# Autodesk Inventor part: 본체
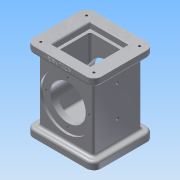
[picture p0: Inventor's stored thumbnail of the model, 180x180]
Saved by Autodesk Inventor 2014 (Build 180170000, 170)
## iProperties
Created: 2017-08
Part Number: 본체
Material: 알루미늄 6061
Document SubType Name: Modeling
Designer: 학생용
Density: 2.71 g/cm^3
Appearance: 알루미늄 - 평지
Mass: 872.328 g
Surface Area: 642.254 cm^2
Volume: 321.892 cm^3
Author: 학생용
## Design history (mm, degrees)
sketch "스케치1"
  geometry: L1 (46, -41)-(-46, -41); L2 (-46, -41)-(-46, 41); L3 (-46, 41)-(46, 41); L4 (46, 41)-(46, -41); L5 (46, -41)-(-46, 41); L6 (-46, -41)-(46, 41); 1 further point
  constraints: 12 end point, 2 midpoint, 2 parallel, 1 horizontal, 1 perpendicular
  dimensions: "d0" = 92 distance of L2.end L3.end; "d1" = 82 distance of L1.end L2.end
extrude "돌출1" new body sketch "스케치1" distance "d2" = 10; taper "d3" = 0 deg
sketch "스케치2"
  geometry: L1 (37, -33)-(-37, -33); L2 (-37, -33)-(-37, 33); L3 (-37, 33)-(37, 33); L4 (37, 33)-(37, -33); L5 (37, -33)-(-37, 33); L6 (-37, -33)-(37, 33); 1 further point
  constraints: 12 end point, 2 midpoint, 2 parallel, 1 horizontal, 1 perpendicular
  dimensions: "d4" = 74 distance of L2.end L3.end; "d5" = 66 distance of L1.end L2.end
extrude "돌출2" join sketch "스케치2" distance "d6" = 88; taper "d7" = 0 deg
sketch "스케치3"
  geometry: L1 (46, -41)-(-46, -41); L2 (-46, -41)-(-46, 41); L3 (-46, 41)-(46, 41); L4 (46, 41)-(46, -41); L5 (46, -41)-(-46, 41); L6 (-46, -41)-(46, 41); 1 further point
  constraints: 12 end point, 2 midpoint, 2 parallel, 1 horizontal, 1 perpendicular
  dimensions: "d8" = 92 distance of L2.end L3.end; "d9" = 82 distance of L1.end L2.end
extrude "돌출3" join sketch "스케치3" distance "d10" = 10; taper "d11" = 0 deg
sketch "스케치5"
  geometry: L1 (24, -24)-(-24, -24); L2 (-24, -24)-(-24, 24); L3 (-24, 24)-(24, 24); L4 (24, 24)-(24, -24); L5 (24, -24)-(-24, 24); L6 (-24, -24)-(24, 24); 1 further point
  constraints: 12 end point, 2 midpoint, 2 parallel, 1 horizontal, 1 perpendicular
  dimensions: "d12" = 48 distance of L2.end L3.end; "d13" = 48 distance of L1.end L2.end
extrude "돌출4" cut sketch "스케치5" distance "d14" = 16; taper "d15" = 0 deg
sketch "스케치6"
  geometry: L1 (26, -26)-(-26, -26); L2 (-26, -26)-(-26, 26); L3 (-26, 26)-(26, 26); L4 (26, 26)-(26, -26); L5 (26, -26)-(-26, 26); L6 (-26, -26)-(26, 26); 1 further point
  constraints: 12 end point, 2 midpoint, 2 parallel, 1 horizontal, 1 perpendicular
  dimensions: "d16" = 52 distance of L2.end L3.end; "d17" = 52 distance of L1.end L2.end
extrude "돌출5" cut sketch "스케치6" distance "d18" = 8; taper "d19" = 0 deg
fillet "모깎기1" dims "d20" = 10
chamfer "모따기1" distance "d21" = 1; stored, may be unused: second distance "d22" = 2, angle "d23" = 45 deg
sketch "스케치7"
  geometry: L1 (22, -22)-(-22, -22); L2 (-22, -22)-(-22, 22); L3 (-22, 22)-(22, 22); L4 (22, 22)-(22, -22); L5 (22, -22)-(-22, 22); L6 (-22, -22)-(22, 22); 1 further point
  constraints: 12 end point, 2 midpoint, 2 parallel, 1 horizontal, 1 perpendicular
  dimensions: "d24" = 44 distance of L2.end L3.end; "d25" = 44 distance of L1.end L2.end
extrude "돌출6" cut sketch "스케치7" distance "d26" = 74; taper "d27" = 0 deg
fillet "모깎기2" dims "d28" = 3
fillet "모깎기3" dims "d29" = 3
fillet "모깎기4" dims "d30" = 3
fillet "모깎기5" dims "d31" = 3
fillet "모깎기6" dims "d32" = 3
sketch "스케치8"
  geometry: A1 r 10 centre (-36, 31) between (-36, 41) and (-46, 31) reference; 2 further points
  constraints: 1 coincident
hole "구멍1" sketch "스케치8" at (-36, 31) diameter "d33" = 3.242; stored, may be unused: countersink angle "d37" = 90 deg, drill point angle "d39" = 118 deg; dims "d34" = 4, "d35" = 4, "d36" = 2, "d38" = 6
sketch "스케치9"
  geometry: A1 r 10 centre (-36, 31) between (-36, 41) and (-46, 31) reference; 2 further points
  constraints: 1 coincident
hole "구멍2" sketch "스케치9" at (-36, 31) diameter "d46" = 3.242; stored, may be unused: countersink angle "d50" = 90 deg, drill point angle "d52" = 118 deg; dims "d47" = 4, "d48" = 4, "d49" = 2, "d51" = 6
fillet "모깎기7" dims "d59" = 3
fillet "모깎기8" dims "d60" = 3
sketch "스케치10"
  geometry: L1 (70, -95)-(-2, -95) reference; C1 r 35 at (34, -41); 2 further points
  constraints: 1 centre point, 1 midpoint, 1 vertical alignment
  dimensions: "d61" = 70 diameter of C1; "d62" = 54 distance from line of L1 C1.centre
extrude "돌출7" cut sketch "스케치10" distance "d63" = 3; taper "d64" = 0 deg
node "작업 평면1"
sketch "스케치11"
  geometry: C1 r 35 at (0, 0) reference; C2 r 24 at (0, 0); 1 further point
  constraints: 1 centre point, 1 coincident
  dimensions: "d65" = 48 diameter of C2
extrude "돌출8" cut sketch "스케치11" stored distance "d66" = 3; taper "d67" = 0 deg
sketch "스케치12" dims "d68" = 58
  geometry: C1 r 35 at (0, 0) reference; 3 further points
  constraints: 2 horizontal alignment, 1 coincident, 2 other
hole "구멍3" sketch "스케치12" at (29, 0) diameter "d69" = 3.242; stored, may be unused: countersink angle "d73" = 90 deg, drill point angle "d75" = 118 deg; dims "d70" = 4, "d71" = 4, "d72" = 2, "d74" = 6
sketch "스케치13"
  geometry: L1 (0, 0)-(72, 0) reference; L2 (-10, 0)-(-10, -7) reference; 2 further points
  constraints: 1 other
  dimensions: "d79" = 46 distance from line of point (36, -4) L2; "d80" = 4 distance from line of L1 point (36, -4)
feature "엠보싱1" sketch "스케치13" dims "d8" = 92, "d9" = 82, "d81" = 0.5, "d82" = 0
sketch "스케치14"
  geometry: L1 (0, 0)-(0, 60) reference; L2 (95, 30)-(0, 30); L3 (-13, -1)-(-13, 61) reference; L4 (95, 61)-(95, -1) reference; 1 further point
  constraints: 2 end point, 1 midpoint, 1 point on line
  dimensions: "d83" = 38 distance from line of point (57, 30) L4
hole "구멍4" sketch "스케치14" at (57, 30) diameter "d84" = 4.134; stored, may be unused: countersink angle "d88" = 90 deg, drill point angle "d90" = 118 deg; dims "d85" = 4, "d86" = 4, "d87" = 2, "d89" = 6
sketch "스케치15"
  geometry: L1 (0, 0)-(0, 60) reference; L2 (95, 30)-(0, 30); C1 r 2.067 at (57, 30) reference; 1 further point
  constraints: 2 end point, 1 midpoint, 1 point on line
  dimensions: "d91" = 42 distance of point (15, 30) C1.centre
hole "구멍5" sketch "스케치15" at (15, 30) diameter "d92" = 4.134; stored, may be unused: countersink angle "d96" = 90 deg, drill point angle "d98" = 118 deg; dims "d93" = 4, "d94" = 4, "d95" = 2, "d97" = 6
node "작업 평면2"
node "작업 평면3"
node "솔리드1"
pattern_linear "직사각형 패턴1" dims "d42" = 72, "d45" = 62
pattern_linear "직사각형 패턴2" dims "d55" = 72, "d58" = 62
mirror "대칭1"
pattern_circular "원형 패턴1" dims angle "d77" = 360 deg
mirror "대칭2"
other parameters: "d99" = -14.5
